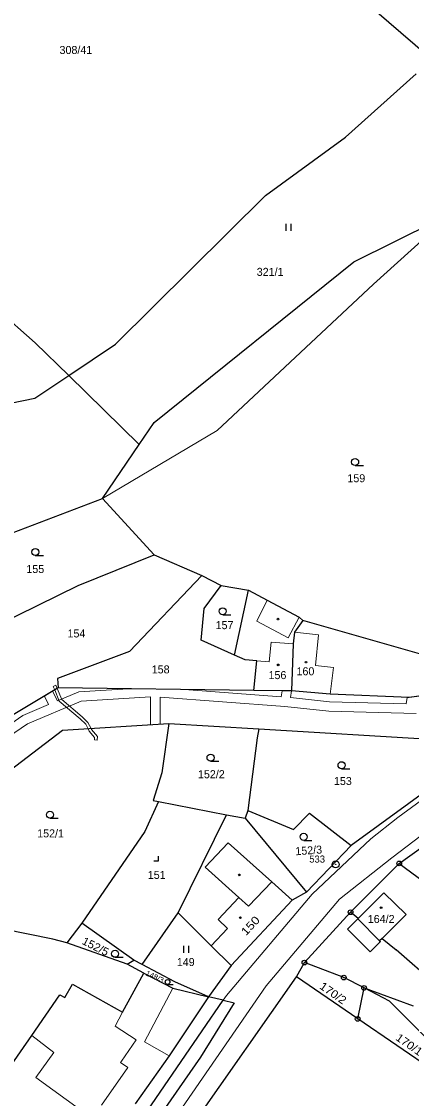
# Model space of a CAD drawing. Extents: x -504006 to -501322, y -1128098 to -1124665.
# Drawn here: x -502422.2 to -502339.3, y -1126531.9 to -1126303.1 of the extents above; entities that cross this region are included whole.
import ezdxf
from ezdxf.enums import TextEntityAlignment as Align

# ---------------------------------------------------------------- set-up
doc = ezdxf.new("R2010")
doc.units = 0
doc.header["$LTSCALE"] = 0.68
for name, color, linetype, lineweight in [('1', 7, 'Continuous', 25), ('13', 7, 'Continuous', 13), ('3', 7, 'Continuous', 25), ('4', 7, 'Continuous', 13), ('5', 7, 'Continuous', 25), ('8', 7, 'Continuous', 25)]:
    doc.layers.add(name, color=color, linetype=linetype, lineweight=lineweight)
doc.layers.add('2', color=7, linetype='Continuous')

msp = doc.modelspace()

# ---------------------------------------------------------------- linework, layer by layer
at = {"layer": '1'}
for p, q in [((-502371.39, -1126279.76), (-502335.48, -1126310.66)), ((-502353.36, -1126327.7), (-502338.37, -1126314.2)), ((-502479.92, -1126318.31), (-502419.28, -1126371.36)), ((-502370.36, -1126340.09), (-502353.36, -1126327.7)), ((-502402.21, -1126371.68), (-502370.36, -1126340.09)), ((-502351.57, -1126354.18), (-502330.66, -1126343.74)), ((-502394.03, -1126388.28), (-502351.57, -1126354.18)), ((-502419.28, -1126371.36), (-502412.17, -1126378.32)), ((-502412.17, -1126378.32), (-502402.21, -1126371.68)), ((-502419.38, -1126383.13), (-502412.17, -1126378.32)), ((-502412.17, -1126378.32), (-502397.21, -1126392.99)), ((-502435.75, -1126386.52), (-502419.38, -1126383.13)), ((-502397.21, -1126392.99), (-502394.03, -1126388.28)), ((-502404.96, -1126404.48), (-502397.21, -1126392.99)), ((-502446.8, -1126420.25), (-502404.96, -1126404.48)), ((-502404.96, -1126404.48), (-502393.98, -1126416.44)), ((-502410.13, -1126422.93), (-502393.98, -1126416.44)), ((-502383.87, -1126420.83), (-502379.74, -1126422.9)), ((-502383.36, -1126427.81), (-502379.74, -1126422.9)), ((-502379.74, -1126422.9), (-502373.95, -1126423.95)), ((-502376.91, -1126437.72), (-502373.95, -1126423.95)), ((-502373.95, -1126423.95), (-502369.99, -1126426.05)), ((-502384.05, -1126434.54), (-502383.36, -1126427.81)), ((-502369.99, -1126426.05), (-502363.22, -1126429.64)), ((-502362.4, -1126430.36), (-502364.22, -1126432.88)), ((-502363.22, -1126429.64), (-502362.4, -1126430.36)), ((-502336.64, -1126437.76), (-502362.4, -1126430.36)), ((-502364.22, -1126432.88), (-502364.47, -1126435.34)), ((-502376.91, -1126437.72), (-502384.05, -1126434.54)), ((-502399.28, -1126436.95), (-502414.52, -1126442.66)), ((-502364.47, -1126435.34), (-502364.8, -1126445.34)), ((-502374.69, -1126438.71), (-502376.91, -1126437.72)), ((-502372.2, -1126438.93), (-502374.69, -1126438.71)), ((-502372.8, -1126445.23), (-502372.2, -1126438.93)), ((-502414.52, -1126442.66), (-502414.39, -1126444.68)), ((-502414.39, -1126444.68), (-502426.09, -1126451.69)), ((-502372.8, -1126445.23), (-502414.39, -1126444.68)), ((-502364.8, -1126445.34), (-502372.8, -1126445.23)), ((-502356.6, -1126446.04), (-502364.8, -1126445.34)), ((-502339.83, -1126446.76), (-502356.6, -1126446.04)), ((-502330.83, -1126445.46), (-502339.83, -1126446.76)), ((-502413.48, -1126453.7), (-502390.91, -1126452.26)), ((-502390.91, -1126452.26), (-502392.37, -1126462.7)), ((-502390.91, -1126452.26), (-502371.74, -1126453.41)), ((-502371.74, -1126453.41), (-502372.16, -1126455.3)), ((-502371.74, -1126453.41), (-502322.35, -1126456.37)), ((-502433.67, -1126469.01), (-502413.48, -1126453.7)), ((-502372.16, -1126455.3), (-502374.1, -1126470.7)), ((-502322.35, -1126456.37), (-502352.18, -1126478.2)), ((-502392.37, -1126462.7), (-502394.21, -1126468.64)), ((-502394.21, -1126468.64), (-502393.12, -1126468.85)), ((-502393.12, -1126468.85), (-502378.61, -1126471.62)), ((-502388.88, -1126492.5), (-502378.61, -1126471.62)), ((-502378.61, -1126471.62), (-502374.68, -1126472.37)), ((-502374.1, -1126470.7), (-502374.68, -1126472.37)), ((-502374.1, -1126470.7), (-502364.42, -1126474.79)), ((-502364.42, -1126474.79), (-502360.98, -1126471.29)), ((-502360.98, -1126471.29), (-502352.18, -1126478.2)), ((-502374.68, -1126472.37), (-502361.61, -1126488.07)), ((-502341.94, -1126481.96), (-502331.78, -1126474.68)), ((-502352.18, -1126478.2), (-502361.61, -1126488.07)), ((-502352.28, -1126492.33), (-502341.94, -1126481.96)), ((-502341.94, -1126481.96), (-502332.95, -1126488.69)), ((-502364.7, -1126489.79), (-502377.63, -1126503.65)), ((-502361.61, -1126488.07), (-502364.7, -1126489.79)), ((-502350.66, -1126493.67), (-502345.2, -1126488.19)), ((-502345.2, -1126488.19), (-502340.5, -1126492.84)), ((-502362.08, -1126503.05), (-502352.28, -1126492.33)), ((-502350.66, -1126493.67), (-502352.28, -1126492.33)), ((-502409.4, -1126494.64), (-502412.57, -1126498.87)), ((-502398.33, -1126502.52), (-502409.4, -1126494.64)), ((-502396.53, -1126503.46), (-502388.88, -1126492.5)), ((-502388.88, -1126492.5), (-502381.93, -1126499.49)), ((-502350.76, -1126493.77), (-502350.66, -1126493.67)), ((-502340.5, -1126492.84), (-502345.56, -1126497.9)), ((-502415.56, -1126498.1), (-502426.04, -1126495.91)), ((-502412.57, -1126498.87), (-502415.56, -1126498.1)), ((-502399.77, -1126503.41), (-502412.57, -1126498.87)), ((-502345.95, -1126498.58), (-502348.11, -1126500.74)), ((-502345.56, -1126497.9), (-502346.1, -1126498.44)), ((-502346.1, -1126498.44), (-502345.95, -1126498.58)), ((-502345.56, -1126497.9), (-502342.62, -1126500.33)), ((-502381.93, -1126499.49), (-502377.63, -1126503.65)), ((-502325.15, -1126515.68), (-502342.62, -1126500.33)), ((-502399.77, -1126503.41), (-502398.33, -1126502.52)), ((-502396.21, -1126505.29), (-502399.77, -1126503.41)), ((-502396.53, -1126503.46), (-502398.33, -1126502.52)), ((-502389.59, -1126507.11), (-502396.53, -1126503.46)), ((-502377.63, -1126503.65), (-502382.43, -1126510.29)), ((-502363.8, -1126506.1), (-502362.08, -1126503.05)), ((-502353.72, -1126506.22), (-502362.08, -1126503.05)), ((-502400.72, -1126513.59), (-502396.21, -1126505.29)), ((-502396.21, -1126505.29), (-502390.04, -1126508.5)), ((-502392.52, -1126547.01), (-502363.8, -1126506.1)), ((-502350.77, -1126515.01), (-502363.8, -1126506.1)), ((-502413.02, -1126510.48), (-502411.39, -1126507.59)), ((-502411.39, -1126507.59), (-502400.72, -1126513.59)), ((-502382.43, -1126510.29), (-502389.59, -1126507.11)), ((-502349.42, -1126508.43), (-502353.72, -1126506.22)), ((-502420.01, -1126518.5), (-502414.02, -1126509.92)), ((-502414.02, -1126509.92), (-502413.02, -1126510.48)), ((-502390.04, -1126508.5), (-502382.43, -1126510.29)), ((-502379.33, -1126511.02), (-502382.43, -1126510.29)), ((-502350.77, -1126515.01), (-502349.42, -1126508.43)), ((-502349.42, -1126508.43), (-502338.96, -1126512.21)), ((-502343.98, -1126511.21), (-502349.42, -1126508.43)), ((-502400.8, -1126542.27), (-502379.33, -1126511.02)), ((-502376.99, -1126511.57), (-502384.2, -1126523.11)), ((-502379.33, -1126511.02), (-502376.99, -1126511.57)), ((-502317.95, -1126537.47), (-502343.98, -1126511.21)), ((-502317.95, -1126537.47), (-502350.77, -1126515.01)), ((-502427.32, -1126528.97), (-502420.01, -1126518.5)), ((-502384.2, -1126523.11), (-502414.86, -1126567.45))]:
    msp.add_line(p, q, dxfattribs=at)
for points in [[(-502393.98, -1126416.44), (-502383.87, -1126420.83), (-502399.28, -1126436.95)], [(-502437.18, -1126436.87), (-502427.37, -1126431.36), (-502410.13, -1126422.93)], [(-502393.12, -1126468.85), (-502396.01, -1126475.2), (-502409.4, -1126494.64)], [(-502348.11, -1126500.74), (-502352.93, -1126495.93), (-502350.76, -1126493.77)], [(-502382.43, -1126510.29), (-502390.84, -1126522.88), (-502398.02, -1126533.04)]]:
    msp.add_lwpolyline(points, dxfattribs=at)
at = {"layer": '13'}
for points in [[(-502415.13, -1126445.13), (-502414.62, -1126444.82), (-502414.9, -1126444.13), (-502415.45, -1126444.36)], [(-502415.13, -1126445.13), (-502414.16, -1126447.49), (-502409.71, -1126451.27), (-502408.56, -1126452.39), (-502408.06, -1126453.35), (-502407.4, -1126453.31), (-502408.08, -1126452.03), (-502409.31, -1126450.83), (-502413.66, -1126447.13), (-502414.62, -1126444.82)], [(-502406.12, -1126455.8), (-502406.04, -1126455), (-502407.29, -1126453.52), (-502407.4, -1126453.31), (-502408.06, -1126453.35), (-502407.79, -1126453.86), (-502406.66, -1126455.2), (-502406.72, -1126455.74)]]:
    msp.add_lwpolyline(points, close=True, dxfattribs=at)
for points in [[(-502399.53, -1126444.88), (-502410.01, -1126445.49), (-502414.58, -1126447.44), (-502415.61, -1126445.41), (-502417.33, -1126446.44), (-502416.43, -1126448.22), (-502421.9, -1126450.53), (-502428.68, -1126455.2)], [(-502427.48, -1126456.8), (-502420.94, -1126452.29), (-502409.55, -1126447.47), (-502394.77, -1126446.6), (-502394.76, -1126452.51), (-502392.76, -1126452.38), (-502392.77, -1126446.62), (-502366.24, -1126448.61), (-502356.89, -1126449.63), (-502338.34, -1126450.15)], [(-502364.8, -1126445.34), (-502366.82, -1126445.31), (-502367.01, -1126446.56), (-502387.59, -1126445.03), (-502399.53, -1126444.88)], [(-502338.17, -1126446.52), (-502339.83, -1126446.76), (-502340.24, -1126446.74), (-502340.45, -1126448.09), (-502356.75, -1126447.63), (-502365.01, -1126446.73), (-502364.8, -1126445.34)]]:
    msp.add_lwpolyline(points, dxfattribs=at)
at = {"layer": '3'}
for p, q in [((-502365.931, -1126347.6), (-502365.931, -1126346.1)), ((-502364.93, -1126347.6), (-502364.93, -1126346.1)), ((-502351.313, -1126397.45), (-502349.563, -1126397.45)), ((-502419.263, -1126416.57), (-502417.513, -1126416.57)), ((-502379.453, -1126429.16), (-502377.703, -1126429.16)), ((-502382.033, -1126460.26), (-502380.283, -1126460.26)), ((-502354.193, -1126461.86), (-502352.443, -1126461.86)), ((-502416.153, -1126472.38), (-502414.403, -1126472.38)), ((-502362.243, -1126477.08), (-502360.493, -1126477.08)), ((-502387.671, -1126500.95), (-502387.671, -1126499.45)), ((-502386.67, -1126500.95), (-502386.67, -1126499.45)), ((-502402.323, -1126501.92), (-502400.573, -1126501.92)), ((-502391.165, -1126507.66), (-502389.993, -1126507.66))]:
    msp.add_line(p, q, dxfattribs=at)
msp.add_lwpolyline([(-502394.081, -1126481.45), (-502393.08, -1126481.45), (-502393.08, -1126480.45)], dxfattribs=at)
for centre, radius in [((-502351.3129, -1126396.6998), 0.75), ((-502419.2629, -1126415.8198), 0.75), ((-502379.4529, -1126428.4098), 0.75), ((-502382.0329, -1126459.5098), 0.75), ((-502354.1929, -1126461.1098), 0.75), ((-502416.1529, -1126471.6298), 0.75), ((-502362.2429, -1126476.3298), 0.75), ((-502402.3229, -1126501.1698), 0.75), ((-502391.1652, -1126507.1574), 0.5025)]:
    msp.add_circle(centre, radius, dxfattribs=at)
at = {"layer": '4'}
for p, q in [((-502347.44, -1126358.94), (-502330.66, -1126343.74)), ((-502380.64, -1126390), (-502347.44, -1126358.94)), ((-502404.96, -1126404.48), (-502380.64, -1126390)), ((-502372.21, -1126430.51), (-502369.99, -1126426.05)), ((-502365.53, -1126434.03), (-502372.21, -1126430.51)), ((-502363.22, -1126429.64), (-502365.53, -1126434.03)), ((-502364.22, -1126432.88), (-502359.07, -1126433.4)), ((-502369.61, -1126439.16), (-502369.14, -1126434.95)), ((-502369.14, -1126434.95), (-502364.47, -1126435.34)), ((-502359.07, -1126433.4), (-502359.76, -1126439.91)), ((-502372.2, -1126438.93), (-502369.61, -1126439.16)), ((-502359.76, -1126439.91), (-502355.92, -1126440.37)), ((-502355.92, -1126440.37), (-502356.6, -1126446.04)), ((-502342.27, -1126472.21), (-502310.67, -1126449.08)), ((-502347.98, -1126476.76), (-502342.27, -1126472.21)), ((-502332.95, -1126472.69), (-502343.54, -1126480.76)), ((-502383.17, -1126482.75), (-502378.28, -1126477.57)), ((-502378.28, -1126477.57), (-502369.01, -1126485.91)), ((-502360.47, -1126488.48), (-502347.98, -1126476.76)), ((-502343.54, -1126480.76), (-502354.6, -1126489.59)), ((-502376, -1126489.19), (-502383.17, -1126482.75)), ((-502373.95, -1126491.02), (-502369.01, -1126485.91)), ((-502369.01, -1126485.91), (-502364.7, -1126489.79)), ((-502380.41, -1126493.92), (-502376, -1126489.19)), ((-502378.65, -1126510.03), (-502360.47, -1126488.48)), ((-502376, -1126489.19), (-502373.95, -1126491.02)), ((-502354.6, -1126489.59), (-502370.24, -1126508)), ((-502378.4, -1126495.79), (-502380.41, -1126493.92)), ((-502350.76, -1126493.77), (-502346.1, -1126498.44)), ((-502381.93, -1126499.49), (-502378.4, -1126495.79)), ((-502370.24, -1126508), (-502396.3, -1126545.8)), ((-502390.04, -1126508.5), (-502396.05, -1126519.89)), ((-502379.33, -1126511.02), (-502378.65, -1126510.03)), ((-502402.32, -1126516.54), (-502400.72, -1126513.59)), ((-502402.32, -1126516.54), (-502397.82, -1126519.46)), ((-502420.01, -1126518.5), (-502415.36, -1126522.15)), ((-502397.82, -1126519.46), (-502400.97, -1126523.96)), ((-502396.05, -1126519.89), (-502390.84, -1126522.88)), ((-502415.36, -1126522.15), (-502419.12, -1126527.46)), ((-502400.97, -1126523.96), (-502401.17, -1126524.25)), ((-502401.17, -1126524.25), (-502399.58, -1126525.35)), ((-502405.22, -1126533.31), (-502399.58, -1126525.35)), ((-502419.12, -1126527.46), (-502409.09, -1126534.74))]:
    msp.add_line(p, q, dxfattribs=at)
at = {"layer": '5'}
for centre in [(-502367.7068, -1126430.0692), (-502367.6468, -1126439.7892), (-502361.7368, -1126439.2192), (-502375.9168, -1126484.4092), (-502345.7868, -1126491.3692), (-502375.6868, -1126493.4992)]:
    msp.add_circle(centre, 0.175, dxfattribs=at)
at = {"layer": '8'}
for centre, radius in [((-502355.46, -1126482.1798), 0.75), ((-502355.46, -1126482.1798), 0.03), ((-502341.94, -1126481.9599), 0.5), ((-502341.94, -1126481.9599), 0.0303), ((-502352.28, -1126492.3299), 0.5), ((-502352.28, -1126492.3299), 0.0303), ((-502362.08, -1126503.0499), 0.5), ((-502362.08, -1126503.0499), 0.0303), ((-502353.72, -1126506.2199), 0.5), ((-502353.72, -1126506.2199), 0.0303), ((-502349.42, -1126508.4299), 0.5), ((-502349.42, -1126508.4299), 0.0303), ((-502350.77, -1126515.0099), 0.5), ((-502350.77, -1126515.0099), 0.0303)]:
    msp.add_circle(centre, radius, dxfattribs=at)

# ---------------------------------------------------------------- texts
at = {"layer": '2'}
for s, p in [('308/41', (-502410.64, -1126310.015)), ('321/1', (-502369.37, -1126357.155)), ('159', (-502351.059, -1126400.995)), ('155', (-502419.269, -1126420.275)), ('157', (-502379.059, -1126432.205)), ('154', (-502410.529, -1126433.965)), ('158', (-502392.629, -1126441.605)), ('156', (-502367.819, -1126442.815)), ('160', (-502361.869, -1126442.005)), ('152/2', (-502381.86, -1126463.875)), ('153', (-502353.909, -1126465.315)), ('152/1', (-502416.02, -1126476.445)), ('151', (-502393.469, -1126485.265)), ('164/2', (-502345.78, -1126494.625)), ('149', (-502387.299, -1126503.775))]:
    msp.add_text(s, height=1.7, dxfattribs=at).set_placement(p, align=Align.CENTER)
msp.add_text('152/3', height=1.7, rotation=4, dxfattribs=at).set_placement((-502361.1193, -1126480.051), align=Align.CENTER)
for s, rotation, width, p in [('150', 47, 1.2, (-502372.953, -1126495.7937)), ('152/5', 333, 1.05, (-502406.8454, -1126500.3687)), ('170/2', 325, 1.1, (-502356.4745, -1126510.2216)), ('170/1', 325, 1.1, (-502340.3045, -1126521.1416))]:
    msp.add_text(s, height=1.7, rotation=rotation, dxfattribs=dict(at, width=width)).set_placement(p, align=Align.CENTER)
at = {"layer": '2', "width": 1.05}
msp.add_text('148/3', height=1.139, rotation=335, dxfattribs=at).set_placement((-502395.94, -1126505.688))
at = {"layer": '8'}
msp.add_text('533', height=1.5, dxfattribs=at).set_placement((-502357.709, -1126481.795), align=Align.RIGHT)

doc.saveas('drawing.dxf')
